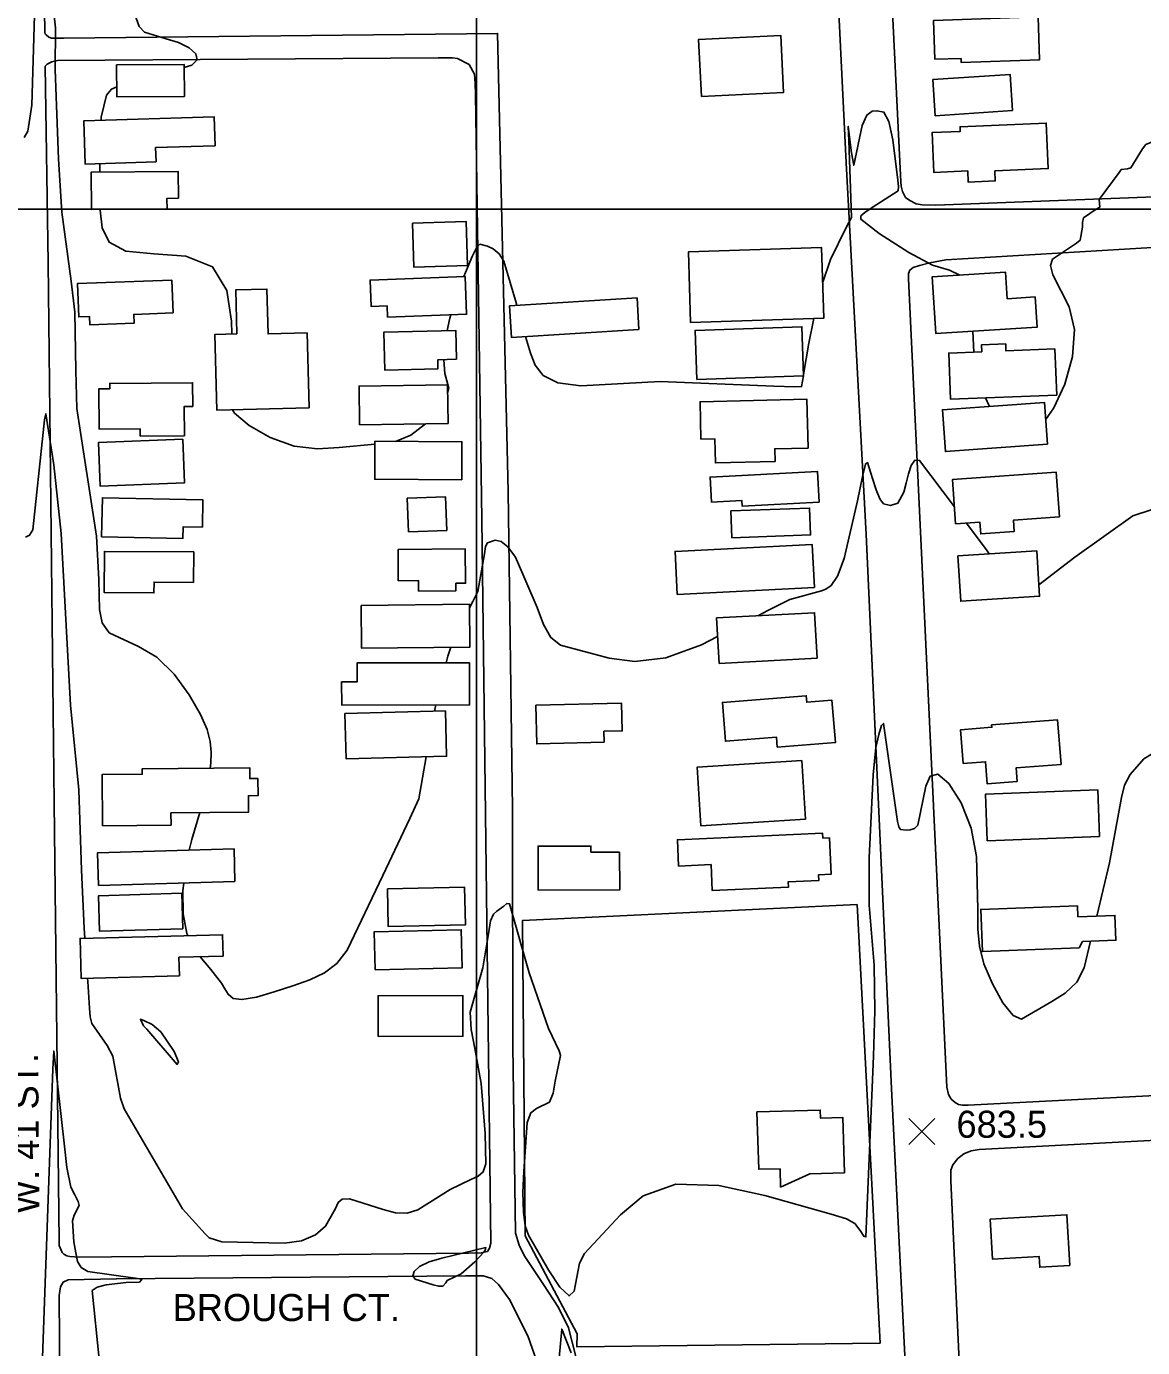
# Model space of a CAD drawing. Extents: x 79600 to 91800, y 75600 to 84400.
# Drawn here: x 80751 to 81369, y 81370 to 82101 of the extents above; entities that cross this region are included whole.
import ezdxf

# ---------------------------------------------------------------- set-up
doc = ezdxf.new("R2010")
doc.units = 0
for name, color, linetype in [('084-085$0$BLDG', 7, 'Continuous'), ('084-085$0$GRID', 7, 'Continuous'), ('084-085$0$INTER', 7, 'Continuous'), ('084-085$0$RECREATION', 7, 'Continuous'), ('084-085$0$ROAD', 7, 'Continuous'), ('084-085$0$ROAD-NAME', 7, 'Continuous'), ('084-085$0$SPOTMARK', 7, 'Continuous'), ('084-085$0$SPOTS', 7, 'Continuous')]:
    doc.layers.add(name, color=color, linetype=linetype)

# ---------------------------------------------------------------- blocks, each defined once
blk = doc.blocks.new('084-085$0$SPOTX')
at = {"layer": '084-085$0$SPOTMARK'}
for p, q in [((-0.37, 0.358), (0.351, -0.358)), ((-0.012, 0), (-0.37, -0.358)), ((-0.012, 0), (0.347, 0.358))]:
    blk.add_line(p, q, dxfattribs=at)

msp = doc.modelspace()

# ---------------------------------------------------------------- linework, layer by layer
at = {"layer": '084-085$0$BLDG'}
for points in [[(81268.45, 82083.56), (81268.53, 82081.26), (81312, 82082.78), (81311.17, 82106.55), (81253.27, 82104.53), (81254.02, 82083.06)], [(81124.65, 82062.47), (81123.09, 82094.06), (81168.58, 82096.3), (81170.14, 82064.71)], [(80838.23, 82062.53), (80800.76, 82062.34), (80800.67, 82079.89), (80838.14, 82080.08)], [(81296.93, 82054.61), (81295.6, 82074.64), (81252.88, 82071.81), (81254.21, 82051.78)], [(80855.18, 82035.21), (80822.29, 82034.13), (80822.55, 82026.28), (80783.22, 82025), (80782.44, 82048.9), (80854.66, 82051.26)], [(81272.13, 82021.2), (81272.4, 82015.03), (81287.44, 82015.68), (81287.2, 82021.27), (81316.74, 82022.56), (81315.64, 82047.74), (81267.92, 82045.66), (81268.03, 82043.13), (81252.42, 82042.45), (81253.38, 82020.38)], [(80834.94, 82006.07), (80828.54, 82006.03), (80828.58, 82000.08), (80786.66, 81999.78), (80786.51, 82020.51), (80834.83, 82020.86)], [(80964.58, 81992.23), (80994.31, 81993.16), (80995.07, 81968.8), (80965.33, 81967.88)], [(81118.66, 81937.39), (81192.47, 81939.76), (81191.21, 81978.8), (81117.4, 81976.43)], [(80831.99, 81942.56), (80810.13, 81941.77), (80810.31, 81936.87), (80785.83, 81935.99), (80785.66, 81940.58), (80779.65, 81940.36), (80778.98, 81958.85), (80831.33, 81960.74)], [(80950.76, 81940.19), (80950.51, 81946.59), (80941.6, 81946.25), (80941.05, 81960.78), (80993.79, 81962.77), (80994.58, 81941.84)], [(81309.6, 81951.43), (81294.07, 81950.45), (81293.15, 81965.1), (81252.44, 81962.52), (81254.42, 81931.24), (81310.65, 81934.8)], [(80867.35, 81931.02), (80866.69, 81955.34), (80883.91, 81955.81), (80884.58, 81930.96), (80906.21, 81931.54), (80907.33, 81890.13), (80856.24, 81888.74), (80855.1, 81930.68)], [(81090.04, 81933.37), (81019.42, 81929), (81018.33, 81946.54), (81088.96, 81950.91)], [(80989.02, 81916.91), (80978.52, 81916.62), (80978.65, 81911.66), (80949.27, 81910.85), (80948.69, 81931.86), (80988.58, 81932.96)], [(81122.05, 81905.76), (81181.27, 81907.8), (81180.34, 81934.96), (81121.11, 81932.92)], [(81320.47, 81922.64), (81293.36, 81921.57), (81293.2, 81925.42), (81279.78, 81924.88), (81279.93, 81921.06), (81261.64, 81920.34), (81262.66, 81894.76), (81321.49, 81897.09)], [(80813.66, 81874.4), (80838.2, 81874.59), (80838.07, 81890.78), (80842.83, 81890.82), (80842.72, 81903.97), (80796.82, 81903.61), (80796.84, 81900.59), (80790.81, 81900.54), (80790.98, 81878.28), (80813.63, 81878.45)], [(80984.25, 81881.36), (80935.26, 81880.7), (80934.97, 81902.07), (80983.96, 81902.73)], [(81124.38, 81872.78), (81132.05, 81872.97), (81132.38, 81859.52), (81165.45, 81860.32), (81165.29, 81867.35), (81183.74, 81867.79), (81183.09, 81894.83), (81123.89, 81893.41)], [(81316.29, 81869.9), (81314.62, 81893.04), (81258.14, 81888.98), (81259.8, 81865.83)], [(80837.31, 81872.65), (80790.65, 81870.93), (80791.54, 81846.71), (80838.21, 81848.44)], [(80991.86, 81850.23), (80943.63, 81850.49), (80943.75, 81871.55), (80991.97, 81871.29)], [(81130.18, 81837.88), (81147.01, 81838.76), (81147.17, 81835.61), (81189.78, 81837.85), (81188.88, 81854.87), (81129.45, 81851.74)], [(81265.44, 81825.77), (81278.89, 81826.72), (81279.35, 81820.26), (81297.94, 81821.57), (81297.5, 81827.81), (81322.98, 81829.6), (81321.24, 81854.36), (81263.72, 81850.32)], [(80848.18, 81823.97), (80837.57, 81824.19), (80837.43, 81817.7), (80792.34, 81818.64), (80792.79, 81840.27), (80848.49, 81839.1)], [(80962.3, 81821.37), (80983.58, 81822.15), (80982.9, 81840.75), (80961.63, 81839.98)], [(81141.54, 81818.1), (81185.13, 81819.67), (81184.6, 81834.54), (81141.01, 81832.98)], [(81111.23, 81786.68), (81187.19, 81790.58), (81185.97, 81814.43), (81110.01, 81810.52)], [(80843.28, 81793.4), (80821.38, 81793.52), (80821.35, 81787.57), (80793.82, 81787.71), (80793.94, 81810.52), (80843.37, 81810.26)], [(80956.72, 81794.3), (80967.92, 81794.4), (80967.98, 81788.54), (80988.65, 81788.74), (80988.61, 81792.9), (80993.97, 81792.95), (80993.79, 81811.93), (80956.56, 81811.59)], [(81310.37, 81810.79), (81266.75, 81808.05), (81268.32, 81782.96), (81311.94, 81785.69)], [(80936.09, 81780.66), (80996.14, 81781.34), (80996.41, 81757.6), (80936.36, 81756.92)], [(81134.39, 81748.56), (81188.69, 81751.39), (81187.37, 81776.57), (81133.07, 81773.73)], [(80925.33, 81738.3), (80933.89, 81738.31), (80933.88, 81748.84), (80996.15, 81748.9), (80996.17, 81725.55), (80925.34, 81725.48)], [(81070.81, 81704.83), (81070.66, 81710.93), (81080.76, 81711.17), (81080.4, 81726.47), (81032.93, 81725.35), (81033.43, 81703.95)], [(81166.64, 81702.07), (81166.18, 81707.71), (81137.95, 81705.44), (81136.23, 81726.88), (81182.67, 81730.61), (81182.96, 81727), (81196.96, 81728.13), (81198.85, 81704.66)], [(80927.12, 81720.84), (80982.81, 81722.24), (80983.44, 81697.14), (80927.75, 81695.74)], [(81299.58, 81683.07), (81282.99, 81681.8), (81282.05, 81694.09), (81269.67, 81693.15), (81268.24, 81711.81), (81285.52, 81713.13), (81285.42, 81714.45), (81321.95, 81717.24), (81323.84, 81692.58), (81298.99, 81690.68)], [(80830.76, 81665.78), (80873.79, 81666.16), (80873.7, 81675.28), (80879.04, 81675.33), (80878.96, 81684.79), (80874.44, 81684.75), (80874.39, 81690.73), (80814.88, 81690.19), (80814.91, 81687.16), (80792.65, 81686.96), (80792.91, 81658.66), (80830.82, 81659)], [(81124.32, 81658.65), (81122.3, 81691.09), (81180.21, 81694.69), (81182.23, 81662.26)], [(81345.24, 81652.75), (81282.96, 81650.29), (81281.94, 81676.1), (81344.22, 81678.56)], [(81191.88, 81651.8), (81195.57, 81651.96), (81196.48, 81631.8), (81189.56, 81631.49), (81189.7, 81628.36), (81172.74, 81627.59), (81172.88, 81624.63), (81130.67, 81622.72), (81130.01, 81637.13), (81111.96, 81636.31), (81111.3, 81650.86), (81191.76, 81654.51)], [(80866.23, 81627.68), (80790.63, 81625.61), (80790.13, 81643.7), (80865.74, 81645.77)], [(81079.34, 81644.06), (81063.4, 81644.04), (81063.39, 81647.4), (81034.17, 81647.37), (81034.19, 81623.03), (81079.36, 81623.07)], [(80950.64, 81623.65), (80993.44, 81624.61), (80993.9, 81603.74), (80951.11, 81602.79)], [(80837.39, 81601.63), (80791.24, 81600.24), (80790.64, 81619.89), (80836.79, 81621.29)], [(81335.71, 81594.48), (81354.27, 81595.19), (81353.74, 81608.99), (81333.16, 81608.2), (81332.93, 81614.32), (81279.41, 81612.28), (81280.3, 81588.91), (81333.88, 81590.96)], [(80943.89, 81578.84), (80992.04, 81579.96), (80991.54, 81601.01), (80943.4, 81599.89)], [(80859.71, 81586.46), (80835.15, 81585.82), (80835.42, 81575.53), (80780.96, 81574.1), (80780.38, 81596.23), (80859.4, 81598.3)], [(80945.52, 81541.98), (80992.53, 81542.03), (80992.5, 81564.54), (80945.5, 81564.49)], [(81168.19, 81468.72), (81168.49, 81458.52), (81184.68, 81465.94), (81203.87, 81466.5), (81202.97, 81497.15), (81190.57, 81496.79), (81190.44, 81501.2), (81155.42, 81500.17), (81156.35, 81468.38)], [(81328.74, 81415.08), (81312.08, 81414.11), (81311.73, 81420.15), (81285.86, 81418.65), (81284.57, 81440.74), (81327.11, 81443.21)]]:
    msp.add_lwpolyline(points, close=True, dxfattribs=at)
at = {"layer": '084-085$0$GRID'}
for p, q in [((81000, 84000), (81000, 80000)), ((85000, 82000), (80000, 82000))]:
    msp.add_line(p, q, dxfattribs=at)
at = {"layer": '084-085$0$INTER'}
for p, q in [((80791.32, 82025.26), (80791.29, 82020.54)), ((81274.96, 81932.54), (81275.47, 81920.89)), ((80976.83, 81722.09), (80977.54, 81725.53))]:
    msp.add_line(p, q, dxfattribs=at)
for points in [[(80783.38, 82154.91), (80786.35, 82150.73), (80809.04, 82112.42), (80813.13, 82101.21), (80816.09, 82098.01), (80828.12, 82094.29), (80835.03, 82092.34), (80840.87, 82089.46), (80844.63, 82086.04), (80845.34, 82082.69), (80842.4, 82079.88), (80838.15, 82078.59)], [(80749.46, 82039.76), (80751.4, 82043.21), (80753.64, 82057.6), (80755.9, 82132.53)], [(80763.87, 82126.9), (80766.75, 82100.46), (80766.54, 82077.37), (80768.54, 82027.7), (80770.4, 81998.47), (80775.41, 81960.15), (80777.57, 81943.11), (80778.15, 81910.79), (80778.65, 81889.66), (80789.47, 81819.02), (80790.85, 81795.04), (80790.97, 81786.51), (80791.24, 81778.3), (80792.69, 81771.08), (80796.55, 81765.48), (80812.86, 81757.86), (80822.95, 81751.94), (80832.58, 81742.48), (80840.89, 81731.13), (80847.15, 81720.32), (80850.86, 81711.88), (80852.56, 81705.29), (80853.05, 81699.44), (80852.92, 81693.26), (80852.42, 81690.53)], [(80800.73, 82067.8), (80797.74, 82066.45), (80795.05, 82063.13), (80792.17, 82051.06), (80792.02, 82049.21)], [(81191.83, 81959.68), (81196.2, 81972.14), (81204.82, 81989.87), (81207.74, 81995.42), (81206.23, 82038.12), (81206.01, 82045.86), (81207.69, 82031.31), (81209.02, 82024.38), (81213.74, 82046.43), (81216.32, 82052.14), (81219.2, 82054.26), (81221.89, 82054.57), (81225.73, 82053.83), (81228.45, 82048.66), (81230.64, 82038.4), (81233.38, 82016.17), (81233.73, 82012.67), (81233.61, 82010.3), (81219.21, 82000.95), (81215.25, 81998.23), (81212.92, 81996.33), (81213.03, 81994.43), (81223.13, 81986.59), (81239.49, 81976.11), (81252.57, 81969.07), (81262.13, 81966.24), (81267.74, 81963.5), (81267.75, 81963.49)], [(81315.32, 81883.4), (81319.92, 81889.98), (81325.97, 81903.18), (81330.27, 81918.41), (81331.33, 81933.34), (81328.34, 81946.03), (81319.23, 81963.71), (81317.99, 81968.91), (81319.05, 81972.31), (81332.51, 81981.15), (81334.42, 81982.83), (81335.75, 81990.1), (81335.77, 81992.76), (81336.27, 81995.22), (81343.37, 82000.11), (81345.41, 82001.18), (81344.98, 82005.38), (81356.07, 82020.33), (81357.19, 82021.93), (81360.69, 82022.35), (81362.51, 82022.95), (81368.92, 82033.55), (81370.85, 82035.81), (81390.28, 82043.91)], [(80791.5, 81999.81), (80791.51, 81999.46), (80792.61, 81989.77), (80796.55, 81981.71), (80805.71, 81976.73), (80821.19, 81975.31), (80838.99, 81973.95), (80853.81, 81968.15), (80861.76, 81955.01), (80864.38, 81937.99), (80864.51, 81930.94)], [(80993.09, 81962.74), (80993.92, 81964.91), (80997.89, 81974.14), (81000.29, 81979.07), (81001.8, 81980.65), (81006.1, 81979.58), (81009.34, 81978.04), (81012.55, 81975.36), (81015.24, 81971.26), (81022.24, 81947.57), (81022.44, 81946.79)], [(80983.83, 81932.82), (80985.19, 81939.64), (80985.77, 81941.51)], [(81181.25, 81908.56), (81184.23, 81925.79), (81186.85, 81939.58)], [(81027.16, 81929.48), (81030, 81920.35), (81032.6, 81913.66), (81037.05, 81907.91), (81045.14, 81903.93), (81057.74, 81902.26), (81101.85, 81904.61), (81164.84, 81901.98), (81176.34, 81901.67), (81180.08, 81901.78), (81181.12, 81907.79)], [(80984.02, 81898.34), (80984.72, 81900.99), (80982.42, 81909.14), (80981.91, 81916.71)], [(81282.03, 81895.53), (81284.04, 81891.09), (81284.18, 81890.85)], [(80750.19, 81818.39), (80752.48, 81819.49), (80754.26, 81822.47), (80760, 81876.44), (80760.75, 81883.43), (80761.52, 81886.81), (80765.88, 81858.41), (80770, 81820.52), (80775.17, 81725.35), (80779.8, 81678.51), (80781.23, 81634.1), (80782.77, 81601.86), (80783.13, 81596.31)], [(80864.84, 81888.97), (80865.91, 81887.12), (80874.03, 81880.31), (80885.78, 81873.55), (80899.02, 81868.77), (80911.92, 81867.27), (80924.04, 81868.01), (80943.74, 81869.91)], [(80955.16, 81871.49), (80963.73, 81874.83), (80971.82, 81881.19)], [(81155.84, 81774.92), (81161.72, 81777.98), (81173.57, 81783.99), (81191.15, 81788.79), (81193.6, 81789.55), (81196.54, 81791.69), (81199.95, 81796.77), (81203.67, 81806.55), (81211.02, 81838.47), (81213.79, 81852.11), (81215.52, 81858.93), (81216.66, 81859.72), (81219.46, 81850.84), (81221.46, 81844.72), (81223.56, 81839.69), (81225.53, 81836.96), (81229.39, 81836.05), (81233.51, 81837.25), (81236.78, 81843.35), (81238.04, 81848.33), (81239.33, 81853.56), (81240.88, 81858.14), (81242.88, 81860.98), (81245.53, 81860.96), (81264.78, 81835.18)], [(81311.55, 81792.01), (81331.5, 81807.34), (81363.71, 81830.23), (81374.35, 81833.78), (81384.84, 81839.37), (81392.09, 81842.64), (81422.34, 81850.11)], [(81271.49, 81826.2), (81282.97, 81810.83), (81283.99, 81809.13)], [(80996.17, 81779.28), (80997.97, 81782.75), (81000.69, 81788.32), (81004.39, 81809.23), (81005.11, 81813.18), (81006.14, 81815.22), (81010.32, 81816.7), (81013.61, 81816), (81017.46, 81813.1), (81021.67, 81807.3), (81033.57, 81779.4), (81037.15, 81770.04), (81041.29, 81762.83), (81046.51, 81758.65), (81073.56, 81751.38), (81087.7, 81749.65), (81104.85, 81751.58), (81124.67, 81758.73), (81133.61, 81763.38)], [(80983.26, 81748.89), (80984.22, 81752.51), (80985.82, 81757.48)], [(81343.64, 81608.6), (81350.77, 81638.02), (81357.4, 81674.25), (81359.09, 81681.05), (81362.19, 81687.02), (81369.81, 81695.67), (81429.75, 81732.09)], [(80784.58, 81574.2), (80784.7, 81572.35), (80785.65, 81557.6), (80786.06, 81552.83), (80786.9, 81549.21), (80795.44, 81536.9), (80798.66, 81530.96), (80802.87, 81507.7), (80804.84, 81501.94), (80837.16, 81446.46), (80849.64, 81432.61), (80852.01, 81430.52), (80858.88, 81428.18), (80893.59, 81427.56), (80903.12, 81428.7), (80910.8, 81432.07), (80916.4, 81436.91), (80921.97, 81446.65), (80923.37, 81450.04), (80925.58, 81451.91), (80929.6, 81452.03), (80948.35, 81446.16), (80955.1, 81444.32), (80961.55, 81444.05), (80967.54, 81445.99), (80985.4, 81457.25), (80996.82, 81462.79), (81000.91, 81464.58), (81003.67, 81466.96), (81005.13, 81471.38), (81004.89, 81488.19), (81002.61, 81515.94), (80999.06, 81535.33), (80997.1, 81545.72), (80996.49, 81555.41), (81003.59, 81579.94), (81006.7, 81598.72), (81007.86, 81605.89), (81009.4, 81609.69), (81011.25, 81611.26), (81015.11, 81614.1), (81016.82, 81615.62), (81018.23, 81615.4), (81029.17, 81577.22), (81039.91, 81546.4), (81045.86, 81533.94), (81046.6, 81531.38), (81043.59, 81517.26), (81042.48, 81510.62), (81040.43, 81505.5), (81033.28, 81502.05), (81030.04, 81499.67), (81028.19, 81494.33), (81026.18, 81467.09), (81025.69, 81455.62), (81025.98, 81444.65), (81026.96, 81437.08), (81028.93, 81431.87), (81040.18, 81412.42), (81046.27, 81403.06), (81051.3, 81398.25), (81054.09, 81400.96), (81057.1, 81416.36), (81059.92, 81421.79), (81079.79, 81443.09), (81092.43, 81453.63), (81110.43, 81460.07), (81134.23, 81459.34), (81159.78, 81453.92), (81196.55, 81443.61), (81205.01, 81441), (81209.67, 81438.31), (81212.63, 81434.58), (81214.54, 81431.41), (81215.72, 81430.99), (81219.93, 81531.02), (81220.67, 81556.18), (81220.36, 81581.42), (81217.62, 81614.63), (81217.65, 81640.89), (81219.78, 81686.89), (81221.3, 81702.04), (81222.84, 81709.22), (81224.37, 81714.08), (81225.59, 81715.31), (81233.26, 81660.93), (81234, 81658.04), (81234.99, 81656.54), (81238.09, 81656.12), (81240.3, 81656.38), (81242.6, 81657.19), (81244.53, 81659.04), (81248.89, 81680.47), (81251.33, 81686.06), (81255.53, 81687.24), (81261.72, 81681.95), (81268.5, 81671.3), (81274.03, 81657.25), (81276.98, 81641.68), (81277.85, 81612.47), (81277.81, 81601.44), (81278.64, 81591.92), (81281.15, 81582.14), (81285.81, 81571.07), (81291.64, 81560.63), (81297.35, 81553.48), (81302.02, 81551.48), (81318.75, 81561.31), (81326.23, 81566), (81332.58, 81571.98), (81336.69, 81579.91), (81340.26, 81594.65)], [(80846.96, 81586.13), (80852.79, 81578.99), (80858.74, 81571.54), (80860.62, 81568.36), (80862.39, 81565.32), (80865.14, 81563.04), (80870.12, 81562.35), (80878.09, 81563.77), (80887.99, 81566.65), (80898.28, 81570.06), (80907.66, 81573.35), (80915.81, 81577.12), (80922.65, 81582.29), (80928.3, 81589.7), (80948.17, 81631.05), (80963.12, 81662.68), (80968.09, 81673.51), (80972.19, 81696.86)], [(80846.7, 81665.92), (80842.33, 81651.08), (80840.94, 81645.09)], [(80837.84, 81626.9), (80837.34, 81622.74), (80837.53, 81609.85), (80839.63, 81598.87), (80840.12, 81597.8)], [(80759.34, 81359.07), (80765.32, 81523.84), (80765.88, 81533.81), (80771.78, 81481.28), (80773.09, 81469.36), (80775.25, 81458.46), (80777.59, 81454.18), (80779.3, 81450.49), (80779.92, 81448.32), (80777.23, 81443.06), (80776.2, 81439.81), (80776.98, 81428.17), (80778.02, 81422.11), (80779.08, 81417.4), (80780.98, 81414.03), (80784.79, 81411.71), (80811, 81408.18), (80813.57, 81407.74), (80814.58, 81407.38), (80813.27, 81405.95), (80806.02, 81405.67), (80794.83, 81404.45), (80789.86, 81403.16), (80787.21, 81401.21), (80791.01, 81363.21)], [(81045.03, 81356.1), (81047.25, 81379.87), (81052.55, 81366.74)]]:
    msp.add_lwpolyline(points, dxfattribs=at)
for points in [[(80817.37, 81545.96), (80834.19, 81526.46), (80834.93, 81527.9), (80832.46, 81533.69), (80825.12, 81544.56), (80820.44, 81548.66), (80815.78, 81550.86), (80813.86, 81551.46), (80815.53, 81547.92)], [(80983.87, 81406.79), (80991.55, 81410.51), (80999.14, 81417.07), (81004.14, 81422.58), (81005.08, 81423.93), (81005.27, 81425.04), (80980.91, 81419.26), (80973.73, 81417.14), (80968.52, 81414.53), (80965.54, 81411.78), (80964.77, 81409.36), (80966.08, 81407.61), (80976, 81404.36), (80979.16, 81403.66), (80981.41, 81403.59), (80983.06, 81405.58)]]:
    msp.add_lwpolyline(points, close=True, dxfattribs=at)
at = {"layer": '084-085$0$RECREATION'}
msp.add_lwpolyline([(81223.6, 81372.16), (81210.85, 81614.96), (81025.43, 81606.08), (81026.97, 81431.49), (81055.71, 81377.19), (81055.57, 81370.16)], close=True, dxfattribs=at)
at = {"layer": '084-085$0$ROAD'}
for points in [[(81388.17, 82756.69), (81214.12, 82675.18), (81210.3, 82673.04), (81208.02, 82669.83), (81206.19, 82665.1), (81204.82, 82658.54), (81203.91, 82651.21), (81235.04, 82015.14), (81235.2, 82012.85), (81235.96, 82009.8), (81237.64, 82006.59), (81240.09, 82004.92), (81243.6, 82003.09), (81246.96, 82002.48), (81254.44, 82002.18), (81400.03, 82007.82)], [(80760.89, 82097.87), (80758.5, 82258.26), (80756.33, 82445.36), (80756.48, 82451.62), (80758.61, 82456.81), (80763.64, 82461.09), (80774.02, 82467.05), (80949.6, 82549.94), (81155.23, 82647.5), (81157.21, 82648.42), (81161.49, 82649.65), (81165.3, 82649.34), (81168.2, 82648.43), (81172.94, 82643.25), (81174.01, 82639.74), (81174.47, 82634.09), (81183.33, 82468.66), (81194.23, 82241.28), (81204.81, 82025.64), (81215.84, 81819.92), (81229.87, 81513.18), (81241.7, 81276.33)], [(81055.11, 81364.67), (81050.98, 81380.54), (81045.47, 81391.83), (81037.22, 81404.64), (81030.95, 81414.09), (81026.52, 81420.65), (81023.62, 81426.45), (81021.63, 81433.01), (81020.15, 81536.64), (81020.03, 81668.04), (81017.57, 81843.7), (81011.69, 82097.34), (80771.47, 82094.82), (80767.65, 82094.82), (80764.6, 82094.81), (80763.08, 82095.27), (80761.55, 82096.64), (80761.07, 82097.14), (80760.89, 82097.87)], [(80761.13, 82079.23), (80762.23, 82080.43), (80764.77, 82081.56), (80767.97, 82082.3), (80978.73, 82083.88), (80986.67, 82083.88), (80989.57, 82083.43), (80995.98, 82080.08), (80998.89, 82074.89), (80999.35, 82069.7), (80999.51, 82063.75), (81002.94, 81828.42), (81007.9, 81427.5), (81007.29, 81424.76), (81006.07, 81422.92), (81002.56, 81422.16), (80995.54, 81422), (80779.9, 81419.81)], [(80779.9, 81419.81), (80774.71, 81420.11), (80773.03, 81420.56), (80771.35, 81421.48), (80770.43, 81422.39), (80768.75, 81426.21), (80768.75, 81428.5), (80766.07, 81671.31), (80762.74, 81970.28), (80761.13, 82079.23)], [(81393.89, 81510.14), (81272.46, 81503.91), (81269.26, 81503.91), (81266.97, 81504.36), (81265.29, 81505.43), (81262.99, 81507.26), (81261.47, 81509.85), (81260.55, 81513.82), (81239.36, 81961.57), (81239.36, 81964.47), (81240.12, 81966.31), (81241.95, 81967.83), (81245.46, 81968.91), (81251.11, 81970.28), (81260.11, 81971.97), (81458.06, 81983.81)], [(81544.87, 81261.24), (81288.56, 81260.66), (81283.83, 81261.26), (81280.47, 81262.17), (81277.57, 81264.46), (81275.28, 81267.36), (81272.53, 81271.78), (81271.3, 81278.34), (81262.73, 81462.08), (81262.73, 81467.88), (81263.94, 81470.78), (81266.69, 81474.3), (81270.04, 81476.89), (81274.01, 81478.58), (81278.59, 81479.34), (81390.78, 81485.24)], [(81034.52, 81358.85), (81028.55, 81376.24), (81018.3, 81396.38), (81012.19, 81404.61), (81008.53, 81407.97), (81003.64, 81409.34), (80994.03, 81409.33), (80800.66, 81407.77), (80773.8, 81407.14), (80771.06, 81405.91), (80769.53, 81403.32), (80768.77, 81398.58), (80769.81, 81273.59)]]:
    msp.add_lwpolyline(points, dxfattribs=at)

# ---------------------------------------------------------------- block references
at = {"layer": '084-085$0$SPOTS', "xscale": 20, "yscale": 20}
msp.add_blockref('084-085$0$SPOTX', (81246.95, 81489.37), dxfattribs=at)

# ---------------------------------------------------------------- texts
at = {"layer": '084-085$0$ROAD-NAME'}
msp.add_text('W. 41 ST.', height=15, rotation=90.48953, dxfattribs=at).set_placement((80757.93, 81443.61))
msp.add_text('BROUGH CT.', height=15, dxfattribs=at).set_placement((80831.73, 81384.33))
at = {"layer": '084-085$0$SPOTS'}
msp.add_text('683.5', height=15, dxfattribs=at).set_placement((81265.92, 81485.84))

doc.saveas('drawing.dxf')
